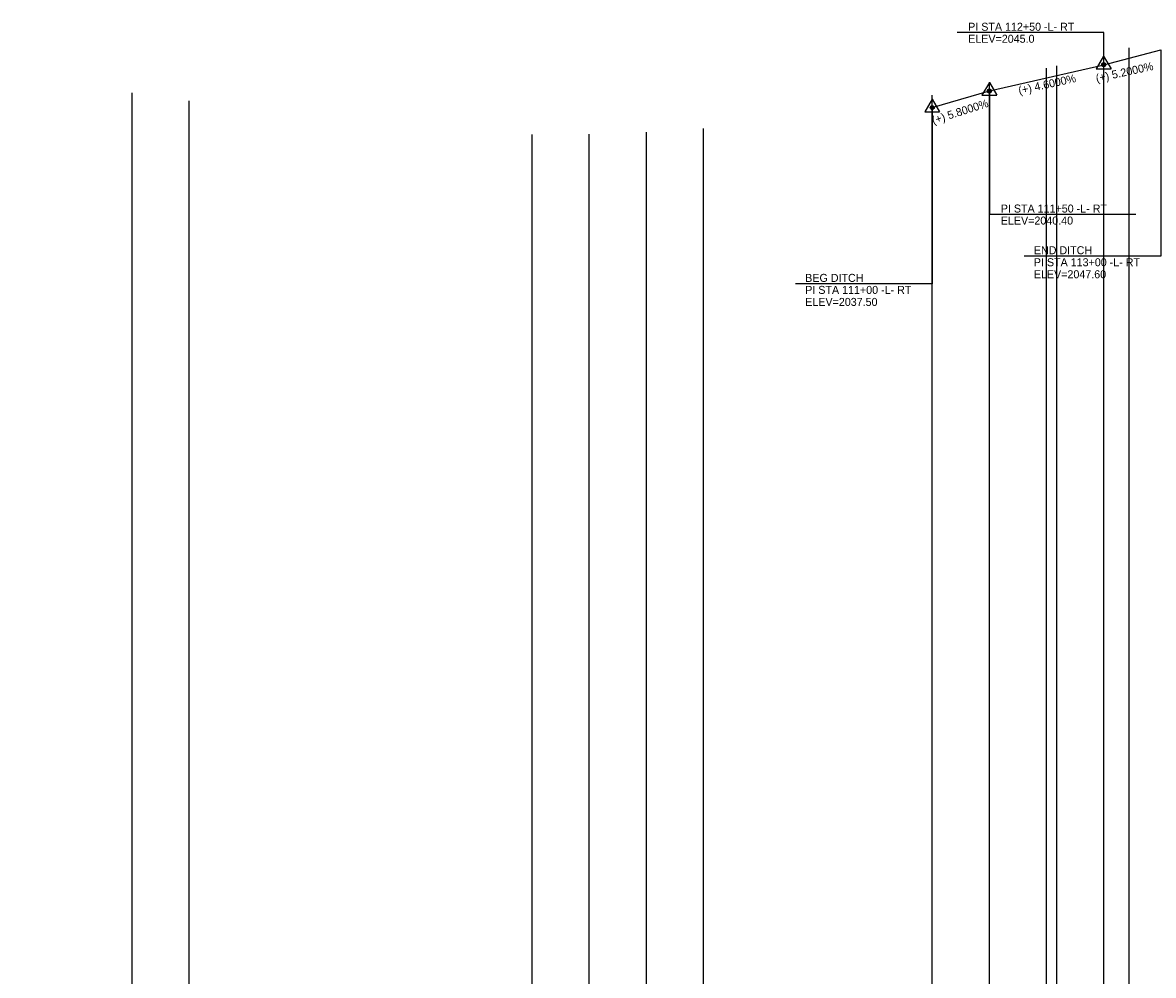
# Model space of a CAD drawing. Extents: x 1025306 to 1036906, y 638983 to 643947.
# Drawn here: x 1034610 to 1035599, y 641918 to 642751 of the extents above; entities that cross this region are included whole.
import ezdxf

# ---------------------------------------------------------------- set-up
doc = ezdxf.new("R2010")
doc.units = 0
for name, color, linetype in [('Default', 7, 'Continuous'), ('Prop Vertical Profile Ditch Grade Right', 7, 'Continuous'), ('Prop Vertical Profile Ditch Grade Right Label', 7, 'Continuous'), ('Prop VPI Ditch Grade Right Label', 7, 'Continuous'), ('Scratch_Level_0', 7, 'Continuous')]:
    doc.layers.add(name, color=color, linetype=linetype)

msp = doc.modelspace()

# ---------------------------------------------------------------- linework, layer by layer
at = {"layer": 'Default'}
for p, q in [((1035555.59, 642721.93), (1035549.14, 642710.73)), ((1035555.59, 642721.93), (1035562.09, 642710.73)), ((1035549.14, 642710.73), (1035562.09, 642710.73)), ((1035455.59, 642698.93), (1035449.14, 642687.73)), ((1035455.59, 642698.93), (1035462.09, 642687.73)), ((1035405.59, 642684.43), (1035399.14, 642673.23)), ((1035405.59, 642684.43), (1035412.09, 642673.23)), ((1035449.14, 642687.73), (1035462.09, 642687.73)), ((1035399.14, 642673.23), (1035412.09, 642673.23))]:
    msp.add_line(p, q, dxfattribs=at)
for centre, radius in [((1035555.6, 642714.44), 1.75), ((1035555.6, 642714.44), 1.2), ((1035455.6, 642691.44), 1.75), ((1035455.6, 642691.44), 1.2), ((1035405.6, 642676.94), 1.75), ((1035405.6, 642676.94), 1.2)]:
    msp.add_circle(centre, radius, dxfattribs=at)
at = {"layer": 'Prop Vertical Profile Ditch Grade Right'}
msp.add_lwpolyline([(1035405.6, 642676.94), (1035455.6, 642691.44), (1035555.6, 642714.44), (1035605.6, 642727.44)], dxfattribs=at)
at = {"layer": 'Prop VPI Ditch Grade Right Label'}
for points in [[(1035555.6, 642714.44), (1035555.6, 642742.62), (1035427.33, 642742.62)], [(1035605.6, 642727.44), (1035605.6, 642546.86), (1035486.06, 642546.86)], [(1035455.6, 642691.94), (1035455.6, 642583.62), (1035583.86, 642583.62)], [(1035405.6, 642676.94), (1035405.6, 642522.67), (1035286.06, 642522.67)]]:
    msp.add_lwpolyline(points, dxfattribs=at)
for centre in [(1035555.6, 642714.44), (1035455.6, 642691.44), (1035405.6, 642676.94)]:
    msp.add_circle(centre, 0.5, dxfattribs=at)
at = {"layer": 'Scratch_Level_0'}
for p, q in [((1034705.6, 639889.44), (1034705.6, 642689.82)), ((1035455.6, 642692.94), (1035455.6, 642699.19)), ((1034755.6, 639889.44), (1034755.6, 642682.72))]:
    msp.add_line(p, q, dxfattribs=at)
for points in [[(1025305.6, 639889.44), (1035578.01, 639889.44), (1035578.01, 642729.05)], [(1025305.6, 639889.44), (1035555.6, 639889.44), (1035555.6, 642723.58)], [(1025305.6, 639889.44), (1035514.6, 639889.44), (1035514.6, 642713.57)], [(1025305.6, 639889.44), (1035505.6, 639889.44), (1035505.6, 642711.37)], [(1025305.6, 639889.44), (1035455.6, 639889.44), (1035455.6, 642699.19)], [(1025305.6, 639889.44), (1035405.6, 639889.44), (1035405.6, 642687.92)], [(1025305.6, 639889.44), (1034755.6, 639889.44), (1034755.6, 642682.72)], [(1025305.6, 639889.44), (1035205.6, 639889.44), (1035205.6, 642658.72)], [(1025305.6, 639889.44), (1035155.6, 639889.44), (1035155.6, 642655.38)], [(1025305.6, 639889.44), (1035105.6, 639889.44), (1035105.6, 642653.62)], [(1025305.6, 639889.44), (1035055.6, 639889.44), (1035055.6, 642653.44)]]:
    msp.add_lwpolyline(points, dxfattribs=at)

# ---------------------------------------------------------------- texts
at = {"layer": 'Prop Vertical Profile Ditch Grade Right Label'}
for s, rotation, p in [('(+) 5.2000%', 12.42594, (1035549.54, 642698.97)), ('(+) 4.6000%', 12.42594, (1035481.85, 642688.37)), ('(+) 5.8000%', 17.74467, (1035406.6, 642662.17))]:
    msp.add_text(s, height=7, rotation=rotation, dxfattribs=at).set_placement(p)
at = {"layer": 'Prop VPI Ditch Grade Right Label'}
for s, p in [('PI STA 112+50 -L- RT', (1035437.06, 642744.13)), ('ELEV=2045.0', (1035437.06, 642733.63)), ('PI STA 111+50 -L- RT', (1035465.6, 642585.14)), ('ELEV=2040.40', (1035465.6, 642574.64)), ('END DITCH', (1035494.51, 642548.66)), ('PI STA 113+00 -L- RT', (1035494.51, 642538.16)), ('BEG DITCH', (1035294.51, 642524.48)), ('ELEV=2047.60', (1035494.51, 642527.66)), ('PI STA 111+00 -L- RT', (1035294.51, 642513.98)), ('ELEV=2037.50', (1035294.51, 642503.48))]:
    msp.add_text(s, height=7, dxfattribs=at).set_placement(p)

doc.saveas('drawing.dxf')
